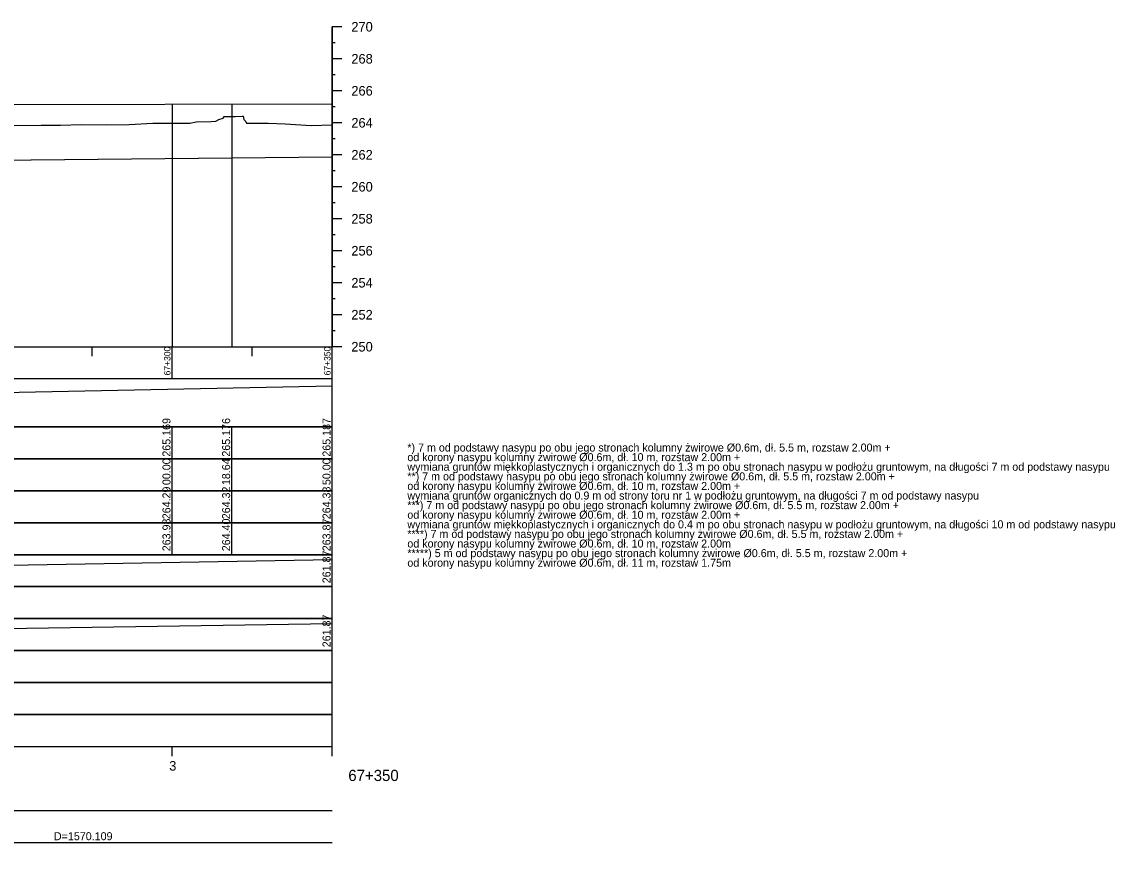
# Model space of a CAD drawing. Extents: x 6531046 to 6533341, y 5514966 to 5518007.
# Drawn here: x 6532999.1 to 6533340.6, y 5517265.4 to 5517524.6 of the extents above; entities that cross this region are included whole.
import ezdxf

# ---------------------------------------------------------------- set-up
doc = ezdxf.new("R2010")
doc.units = 0
for name, color, linetype in [('IR_default', 7, 'Continuous'), ('TOR_PROF-drenokolektory', 7, 'Continuous'), ('TOR_PROF-rowy otwarte', 7, 'Continuous'), ('TOR_PROF-tabelka-geometria T1', 7, 'Continuous'), ('TOR_PROF-tabelka-kilometracja', 7, 'Continuous'), ('TOR_PROF-tabelka-odleglosci T1', 7, 'Continuous'), ('TOR_PROF-tabelka-pochylenia proj T1', 7, 'Continuous'), ('TOR_PROF-tabelka-rodzaj rowu T1', 7, 'Continuous'), ('TOR_PROF-tabelka-rowyT1', 7, 'Continuous'), ('TOR_PROF-tabelka-rzedne proj T1', 7, 'Continuous'), ('TOR_PROF-tabelka-teren istniejacy T1', 7, 'Continuous'), ('TOR_PROF-tabelka-warstwa ochronna T1', 7, 'Continuous'), ('TOR_PROF-tor projektowany', 7, 'Continuous'), ('TOR_PROF-uklad odniesienia', 7, 'Continuous'), ('TOR_PROF-warstwa ochronna', 7, 'Continuous'), ('TOR_PROF-wzocnienia podtorza', 7, 'Continuous')]:
    doc.layers.add(name, color=color, linetype=linetype)

msp = doc.modelspace()

# ---------------------------------------------------------------- linework, layer by layer
at = {"layer": 'IR_default'}
msp.add_lwpolyline([(6532996.11, 5517492.28), (6533005.14, 5517492.39), (6533005.79, 5517492.38), (6533011.21, 5517492.3), (6533017.73, 5517492.53), (6533025.6, 5517492.46), (6533032.65, 5517492.55), (6533039.97, 5517492.94), (6533046.36, 5517493.01), (6533051.56, 5517493), (6533053.59, 5517493.36), (6533058.25, 5517493.49), (6533059.7, 5517493.59), (6533060.62, 5517494.08), (6533062.03, 5517494.54), (6533062.31, 5517495.05), (6533062.75, 5517495.06), (6533065.78, 5517495.08), (6533067.92, 5517495.15), (6533068.24, 5517495.17), (6533068.47, 5517494.11), (6533069.08, 5517493.49), (6533069.32, 5517492.97), (6533076.01, 5517493), (6533081.37, 5517492.79), (6533089.49, 5517492.27), (6533096.02, 5517492.43)], dxfattribs=at)
at = {"layer": 'TOR_PROF-drenokolektory'}
msp.add_lwpolyline([(6533096.02, 5517523.1), (6533096.02, 5517428.1), (6533096.02, 5517423.1), (6533096.02, 5517423.1)], dxfattribs=at)
at = {"layer": 'TOR_PROF-rowy otwarte'}
for p, q in [((6532646.02, 5517477.85), (6533096.02, 5517482.42)), ((6532698.02, 5517478.4), (6533096.02, 5517482.43))]:
    msp.add_line(p, q, dxfattribs=at)
msp.add_lwpolyline([(6533096.02, 5517482.43), (6533096.02, 5517428.1), (6533096.02, 5517423.1), (6533096.02, 5517423.1)], dxfattribs=at)
msp.add_lwpolyline([(6533096.02, 5517482.43), (6533096.02, 5517428.1), (6533096.02, 5517423.1), (6533096.02, 5517423.1)], dxfattribs=at)
at = {"layer": 'TOR_PROF-tabelka-geometria T1'}
for points in [[(6531095.09, 5517278.1), (6533095.09, 5517278.1)], [(6531096.02, 5517278.1), (6533096.02, 5517278.1)], [(6531096.02, 5517268.1), (6533096.02, 5517268.1)], [(6531567.73, 5517268.1), (6532256.58, 5517268.1), (6532256.58, 5517270.76), (6532341.58, 5517270.76), (6532341.58, 5517268.1), (6532431.02, 5517268.1), (6532431.02, 5517265.43), (6532516.02, 5517265.43), (6532516.02, 5517268.1), (6532676.02, 5517268.1), (6532676.02, 5517265.43), (6532761.02, 5517265.43), (6532761.02, 5517268.1), (6532850.47, 5517268.1), (6532850.47, 5517270.76), (6532935.47, 5517270.76), (6532935.47, 5517268.1), (6533096.02, 5517268.1)]]:
    msp.add_lwpolyline(points, dxfattribs=at)
at = {"layer": 'TOR_PROF-tabelka-kilometracja'}
for points in [[(6533046.02, 5517295.1), (6533046.02, 5517298.1)], [(6533096.02, 5517295.1), (6533096.02, 5517298.1)]]:
    msp.add_lwpolyline(points, dxfattribs=at)
at = {"layer": 'TOR_PROF-tabelka-odleglosci T1'}
msp.add_lwpolyline([(6531096.02, 5517378.1), (6533096.02, 5517378.1), (6533096.02, 5517388.1), (6531096.02, 5517388.1)], close=True, dxfattribs=at)
for points in [[(6533046.02, 5517378.1), (6533046.02, 5517388.1)], [(6533064.66, 5517378.1), (6533064.66, 5517388.1)], [(6533096.02, 5517378.1), (6533096.02, 5517388.1)]]:
    msp.add_lwpolyline(points, dxfattribs=at)
at = {"layer": 'TOR_PROF-tabelka-pochylenia proj T1'}
msp.add_lwpolyline([(6531096.02, 5517398.1), (6533096.02, 5517398.1), (6533096.02, 5517413.1), (6531096.02, 5517413.1)], close=True, dxfattribs=at)
msp.add_lwpolyline([(6532576.02, 5517400.35), (6533096.02, 5517410.85)], dxfattribs=at)
at = {"layer": 'TOR_PROF-tabelka-rodzaj rowu T1'}
for points in [[(6531096.02, 5517338.1), (6533096.02, 5517338.1), (6533096.02, 5517348.1), (6531096.02, 5517348.1)], [(6531096.02, 5517318.1), (6533096.02, 5517318.1), (6533096.02, 5517328.1), (6531096.02, 5517328.1)]]:
    msp.add_lwpolyline(points, close=True, dxfattribs=at)
for points in [[(6533096.02, 5517338.1), (6533096.02, 5517348.1)], [(6533096.02, 5517318.1), (6533096.02, 5517328.1)]]:
    msp.add_lwpolyline(points, dxfattribs=at)
at = {"layer": 'TOR_PROF-tabelka-rowyT1'}
for points in [[(6531096.02, 5517348.1), (6533096.02, 5517348.1), (6533096.02, 5517358.1), (6531096.02, 5517358.1)], [(6531096.02, 5517328.1), (6533096.02, 5517328.1), (6533096.02, 5517338.1), (6531096.02, 5517338.1)]]:
    msp.add_lwpolyline(points, close=True, dxfattribs=at)
for points in [[(6532698.02, 5517349.6), (6533096.02, 5517356.6)], [(6533096.02, 5517348.1), (6533096.02, 5517358.1)], [(6532639.02, 5517329.6), (6533096.02, 5517336.6)], [(6533096.02, 5517328.1), (6533096.02, 5517338.1)]]:
    msp.add_lwpolyline(points, dxfattribs=at)
at = {"layer": 'TOR_PROF-tabelka-rzedne proj T1'}
msp.add_lwpolyline([(6531096.02, 5517388.1), (6533096.02, 5517388.1), (6533096.02, 5517398.1), (6531096.02, 5517398.1)], close=True, dxfattribs=at)
for points in [[(6533046.02, 5517388.1), (6533046.02, 5517398.1)], [(6533064.66, 5517388.1), (6533064.66, 5517398.1)], [(6533096.02, 5517388.1), (6533096.02, 5517398.1)]]:
    msp.add_lwpolyline(points, dxfattribs=at)
at = {"layer": 'TOR_PROF-tabelka-teren istniejacy T1'}
for points in [[(6531096.02, 5517368.1), (6533096.02, 5517368.1), (6533096.02, 5517378.1), (6531096.02, 5517378.1)], [(6531096.02, 5517358.1), (6533096.02, 5517358.1), (6533096.02, 5517368.1), (6531096.02, 5517368.1)]]:
    msp.add_lwpolyline(points, close=True, dxfattribs=at)
for points in [[(6533046.02, 5517368.1), (6533046.02, 5517378.1)], [(6533064.66, 5517368.1), (6533064.66, 5517378.1)], [(6533096.02, 5517368.1), (6533096.02, 5517378.1)], [(6533046.02, 5517358.1), (6533046.02, 5517368.1)], [(6533064.66, 5517358.1), (6533064.66, 5517368.1)], [(6533096.02, 5517358.1), (6533096.02, 5517368.1)]]:
    msp.add_lwpolyline(points, dxfattribs=at)
at = {"layer": 'TOR_PROF-tabelka-warstwa ochronna T1'}
for points in [[(6533064.66, 5517498.98), (6533064.66, 5517428.1), (6533064.66, 5517423.1), (6533064.66, 5517423.1)], [(6533096.02, 5517499.03), (6533096.02, 5517428.1), (6533096.02, 5517423.1), (6533096.02, 5517423.1)], [(6533096.02, 5517308.1), (6533096.02, 5517318.1)]]:
    msp.add_lwpolyline(points, dxfattribs=at)
msp.add_lwpolyline([(6531096.02, 5517308.1), (6533096.02, 5517308.1), (6533096.02, 5517318.1), (6531096.02, 5517318.1)], close=True, dxfattribs=at)
at = {"layer": 'TOR_PROF-tor projektowany'}
msp.add_line((6532576.02, 5517498.1), (6533096.02, 5517499.03), dxfattribs=at)
for points in [[(6533046.02, 5517498.94), (6533046.02, 5517428.1), (6533046.02, 5517423.1), (6533046.02, 5517423.1)], [(6533064.66, 5517498.98), (6533064.66, 5517428.1), (6533064.66, 5517423.1), (6533064.66, 5517423.1)], [(6533096.02, 5517499.03), (6533096.02, 5517428.1), (6533096.02, 5517423.1), (6533096.02, 5517423.1)]]:
    msp.add_lwpolyline(points, dxfattribs=at)
at = {"layer": 'TOR_PROF-uklad odniesienia'}
for p, q in [((6533096.02, 5517423.1), (6533096.02, 5517523.1)), ((6533099.02, 5517523.1), (6533096.02, 5517523.1)), ((6533097.02, 5517518.1), (6533096.02, 5517518.1)), ((6533099.02, 5517513.1), (6533096.02, 5517513.1)), ((6533097.02, 5517508.1), (6533096.02, 5517508.1)), ((6533099.02, 5517503.1), (6533096.02, 5517503.1)), ((6533097.02, 5517498.1), (6533096.02, 5517498.1)), ((6533099.02, 5517493.1), (6533096.02, 5517493.1)), ((6533097.02, 5517488.1), (6533096.02, 5517488.1)), ((6533099.02, 5517483.1), (6533096.02, 5517483.1)), ((6533097.02, 5517478.1), (6533096.02, 5517478.1)), ((6533099.02, 5517473.1), (6533096.02, 5517473.1)), ((6533097.02, 5517468.1), (6533096.02, 5517468.1)), ((6533099.02, 5517463.1), (6533096.02, 5517463.1)), ((6533097.02, 5517458.1), (6533096.02, 5517458.1)), ((6533099.02, 5517453.1), (6533096.02, 5517453.1)), ((6533097.02, 5517448.1), (6533096.02, 5517448.1)), ((6533099.02, 5517443.1), (6533096.02, 5517443.1)), ((6533097.02, 5517438.1), (6533096.02, 5517438.1)), ((6533099.02, 5517433.1), (6533096.02, 5517433.1)), ((6533097.02, 5517428.1), (6533096.02, 5517428.1)), ((6531096.02, 5517423.1), (6533096.02, 5517423.1)), ((6533021.02, 5517420.1), (6533021.02, 5517423.1)), ((6533046.02, 5517413.1), (6533046.02, 5517423.1)), ((6533071.02, 5517420.1), (6533071.02, 5517423.1)), ((6533099.02, 5517423.1), (6533096.02, 5517423.1)), ((6533096.02, 5517413.1), (6533096.02, 5517423.1))]:
    msp.add_line(p, q, dxfattribs=at)
at = {"layer": 'TOR_PROF-wzocnienia podtorza'}
msp.add_lwpolyline([(6531096.02, 5517298.1), (6533096.02, 5517298.1), (6533096.02, 5517308.1), (6531096.02, 5517308.1)], close=True, dxfattribs=at)

# ---------------------------------------------------------------- texts
at = {"layer": 'TOR_PROF-tabelka-geometria T1'}
msp.add_text('D=1570.109', height=2.5, dxfattribs=at).set_placement((6533009.11, 5517268.85))
at = {"layer": 'TOR_PROF-tabelka-kilometracja'}
msp.add_text('3', height=3, dxfattribs=at).set_placement((6533045.13, 5517290.6))
msp.add_text('67+350', height=3.5, rotation=360, dxfattribs=at).set_placement((6533101.07, 5517287.35))
at = {"layer": 'TOR_PROF-tabelka-odleglosci T1'}
for s, p in [('00.00', (6533045.52, 5517379.84)), ('18.64', (6533064.16, 5517379.84)), ('50.00', (6533095.52, 5517379.84))]:
    msp.add_text(s, height=2.5, rotation=90, dxfattribs=at).set_placement(p)
at = {"layer": 'TOR_PROF-tabelka-rowyT1'}
for p in [(6533095.52, 5517349.16), (6533095.52, 5517329.16)]:
    msp.add_text('261.87', height=2.5, rotation=90, dxfattribs=at).set_placement(p)
at = {"layer": 'TOR_PROF-tabelka-rzedne proj T1'}
for s, p in [('265.169', (6533045.52, 5517388.73)), ('265.176', (6533064.16, 5517388.73)), ('265.187', (6533095.52, 5517388.73))]:
    msp.add_text(s, height=2.5, rotation=90, dxfattribs=at).set_placement(p)
at = {"layer": 'TOR_PROF-tabelka-teren istniejacy T1'}
for s, p in [('264.29', (6533045.52, 5517369.16)), ('264.32', (6533064.16, 5517369.17)), ('264.38', (6533095.52, 5517369.16)), ('263.98', (6533045.52, 5517359.16)), ('264.40', (6533064.16, 5517359.16)), ('263.87', (6533095.52, 5517359.16))]:
    msp.add_text(s, height=2.5, rotation=90, dxfattribs=at).set_placement(p)
at = {"layer": 'TOR_PROF-uklad odniesienia'}
for s, p in [('270', (6533102.02, 5517521.6)), ('268', (6533102.02, 5517511.6)), ('266', (6533102.02, 5517501.6)), ('264', (6533102.02, 5517491.6)), ('262', (6533102.02, 5517481.6)), ('260', (6533102.02, 5517471.6)), ('258', (6533102.02, 5517461.6)), ('256', (6533102.02, 5517451.6)), ('254', (6533102.02, 5517441.6)), ('252', (6533102.02, 5517431.6)), ('250', (6533102.02, 5517421.6))]:
    msp.add_text(s, height=3, dxfattribs=at).set_placement(p)
for s, p in [('67+300', (6533045.52, 5517414.12)), ('67+350', (6533095.52, 5517414.12))]:
    msp.add_text(s, height=2, rotation=90, dxfattribs=at).set_placement(p)
at = {"layer": 'TOR_PROF-warstwa ochronna'}
for s, p in [('*) 7 m od podstawy nasypu po obu jego stronach kolumny żwirowe Ø0.6m, dł. 5.5 m, rozstaw 2.00m +', (6533119.52, 5517390.33)), ('od korony nasypu kolumny żwirowe Ø0.6m, dł. 10 m, rozstaw 2.00m +', (6533119.52, 5517387.33)), ('wymiana gruntów miękkoplastycznych i organicznych do 1.3 m po obu stronach nasypu w podłożu gruntowym, na długości 7 m od podstawy nasypu', (6533119.52, 5517384.33)), ('**) 7 m od podstawy nasypu po obu jego stronach kolumny żwirowe Ø0.6m, dł. 5.5 m, rozstaw 2.00m +', (6533119.52, 5517381.33)), ('od korony nasypu kolumny żwirowe Ø0.6m, dł. 10 m, rozstaw 2.00m +', (6533119.52, 5517378.33)), ('wymiana gruntów organicznych do 0.9 m od strony toru nr 1 w podłożu gruntowym, na długości 7 m od podstawy nasypu', (6533119.52, 5517375.33)), ('***) 7 m od podstawy nasypu po obu jego stronach kolumny żwirowe Ø0.6m, dł. 5.5 m, rozstaw 2.00m +', (6533119.52, 5517372.33)), ('od korony nasypu kolumny żwirowe Ø0.6m, dł. 10 m, rozstaw 2.00m +', (6533119.52, 5517369.33)), ('wymiana gruntów miękkoplastycznych i organicznych do 0.4 m po obu stronach nasypu w podłożu gruntowym, na długości 10 m od podstawy nasypu', (6533119.52, 5517366.33)), ('****) 7 m od podstawy nasypu po obu jego stronach kolumny żwirowe Ø0.6m, dł. 5.5 m, rozstaw 2.00m +', (6533119.52, 5517363.33)), ('*****) 5 m od podstawy nasypu po obu jego stronach kolumny żwirowe Ø0.6m, dł. 5.5 m, rozstaw 2.00m +', (6533119.52, 5517357.33)), ('od korony nasypu kolumny żwirowe Ø0.6m, dł. 10 m, rozstaw 2.00m ', (6533119.52, 5517360.33)), ('od korony nasypu kolumny żwirowe Ø0.6m, dł. 11 m, rozstaw 1.75m', (6533119.52, 5517354.33))]:
    msp.add_text(s, height=2.5, rotation=360, dxfattribs=at).set_placement(p)

doc.saveas('drawing.dxf')
